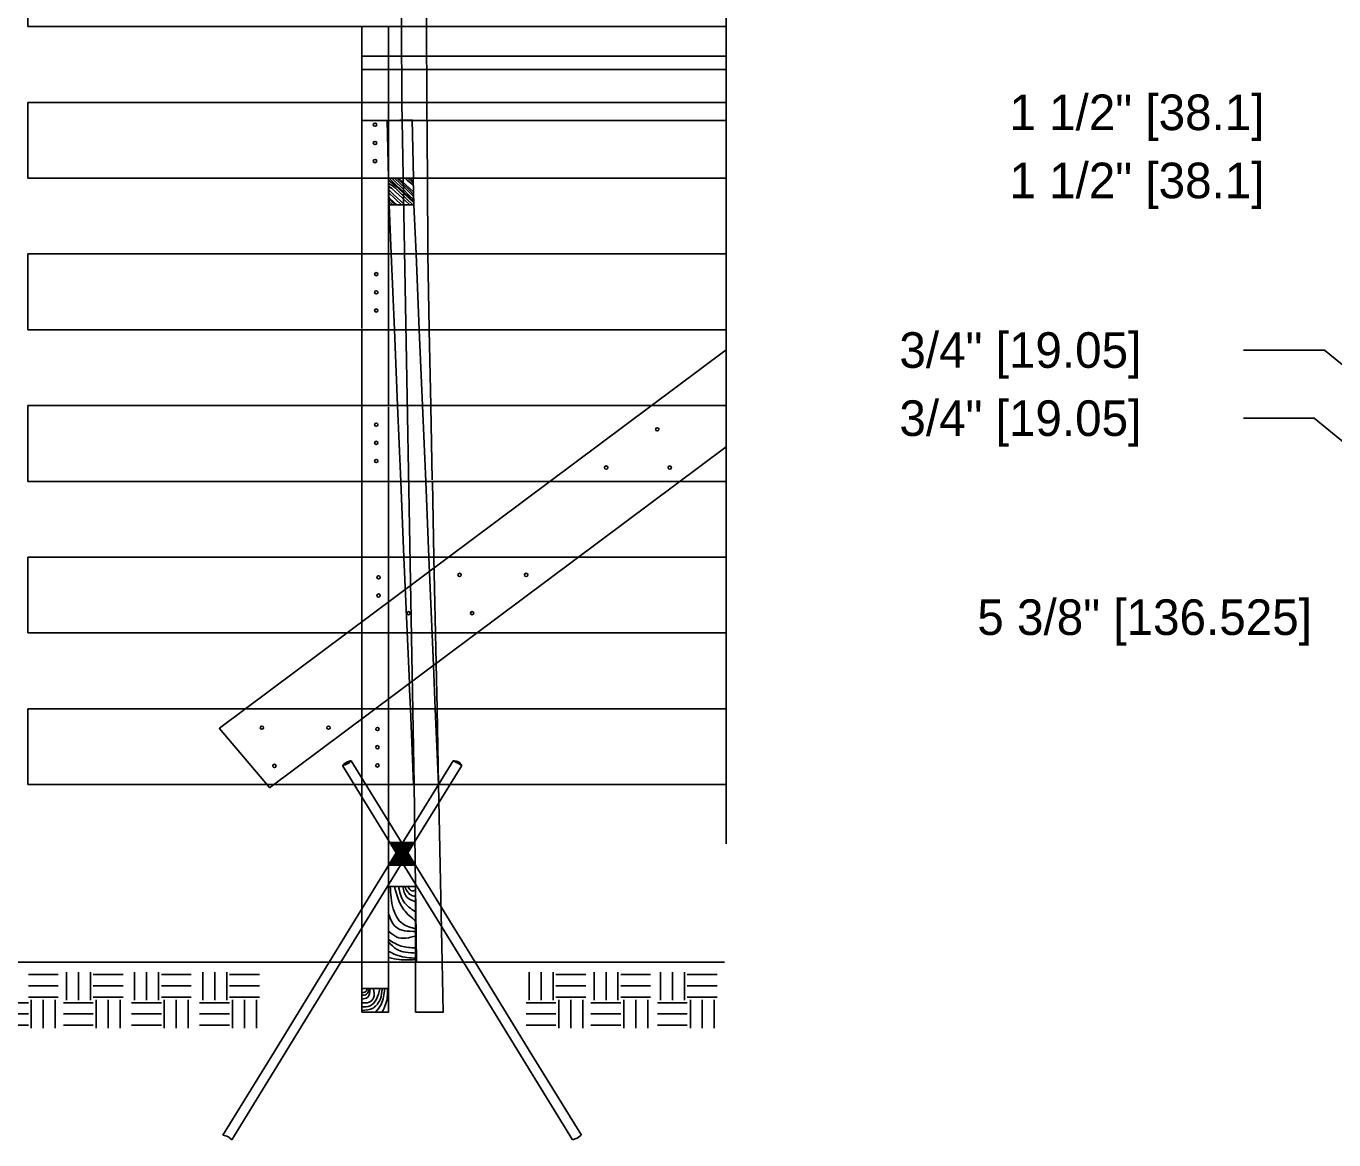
# Model space of a CAD drawing. Extents: x 49991.4 to 50021, y 49987.6 to 50011.4.
# Drawn here: x 50005.062 to 50007.266, y 49994.072 to 49995.949 of the extents above; entities that cross this region are included whole.
import ezdxf

# ---------------------------------------------------------------- set-up
doc = ezdxf.new("R2010")
doc.units = 0
for name, color, linetype in [('Level 1', 7, 'Continuous'), ('Level 2', 7, 'Continuous'), ('Level 3', 7, 'Continuous'), ('Level 4', 7, 'Continuous'), ('Level 6', 7, 'Continuous')]:
    doc.layers.add(name, color=color, linetype=linetype)

msp = doc.modelspace()

# ---------------------------------------------------------------- linework, layer by layer
at = {"layer": 'Level 1'}
for p, q in [((50005.0654, 49996.076), (50005.0654, 49995.9482)), ((50005.0654, 49995.9482), (50006.2419, 49995.9482)), ((50005.6278, 49995.9482), (50005.6278, 49995.8204)), ((50005.6732, 49995.8204), (50005.6732, 49995.9482)), ((50005.6955, 49995.8204), (50005.6947, 49995.9482)), ((50005.7375, 49995.8204), (50005.7367, 49995.9482)), ((50005.6732, 49995.898), (50005.695, 49995.898)), ((50005.737, 49995.898), (50006.2419, 49995.898)), ((50005.6952, 49995.8757), (50005.6732, 49995.8757)), ((50005.7372, 49995.8757), (50006.2419, 49995.8757)), ((50005.0654, 49995.8204), (50005.0654, 49995.6928)), ((50005.0654, 49995.8204), (50006.2419, 49995.8204)), ((50005.0654, 49995.6928), (50006.2419, 49995.6928)), ((50005.6278, 49995.6936), (50005.6278, 49995.5646)), ((50005.6738, 49995.6479), (50005.6729, 49995.6928)), ((50005.6732, 49995.6928), (50005.6732, 49995.5646)), ((50005.7158, 49995.6479), (50005.7146, 49995.6928)), ((50005.7392, 49995.565), (50005.7384, 49995.6928)), ((50005.6738, 49995.6479), (50005.7158, 49995.6479)), ((50005.6738, 49995.6479), (50005.6773, 49995.565)), ((50005.7158, 49995.6479), (50005.7193, 49995.565)), ((50005.0654, 49995.565), (50005.0654, 49995.4372)), ((50005.0654, 49995.565), (50006.2419, 49995.565)), ((50005.6773, 49995.565), (50005.6828, 49995.4372)), ((50005.0654, 49995.4372), (50006.2419, 49995.4372)), ((50005.6278, 49995.4372), (50005.6278, 49995.3094)), ((50005.6732, 49995.3094), (50005.6732, 49995.4372)), ((50005.6828, 49995.4372), (50005.6881, 49995.3094)), ((50005.7248, 49995.4372), (50005.7301, 49995.3094)), ((50005.7443, 49995.3094), (50005.7417, 49995.4372)), ((50005.3881, 49994.7655), (50006.2419, 49995.4032)), ((50005.0654, 49995.3094), (50005.0654, 49995.1816)), ((50005.0654, 49995.3094), (50006.1163, 49995.3094)), ((50005.4726, 49994.6654), (50006.2419, 49995.2399)), ((50005.0654, 49995.1816), (50005.9454, 49995.1816)), ((50005.6278, 49995.1816), (50005.6278, 49995.054)), ((50005.6732, 49995.054), (50005.6732, 49995.1816)), ((50005.6936, 49995.1816), (50005.6989, 49995.054)), ((50005.7356, 49995.1816), (50005.7409, 49995.054)), ((50005.7493, 49995.054), (50005.747, 49995.1816)), ((50006.1638, 49995.1816), (50006.2419, 49995.1816)), ((50005.0654, 49995.054), (50005.0654, 49994.9262)), ((50005.7743, 49995.054), (50005.0654, 49995.054)), ((50005.9927, 49995.054), (50006.2419, 49995.054)), ((50005.0654, 49994.9262), (50005.6032, 49994.9262)), ((50005.8218, 49994.9262), (50006.2419, 49994.9262)), ((50005.7487, 49994.8716), (50005.7518, 49994.7984)), ((50005.7547, 49994.7984), (50005.753, 49994.8748)), ((50005.708, 49994.8412), (50005.7098, 49994.7984)), ((50005.6732, 49994.7984), (50005.6732, 49994.8152)), ((50005.0654, 49994.7984), (50005.0654, 49994.6706)), ((50005.0654, 49994.7984), (50005.4321, 49994.7984)), ((50005.4215, 49994.7984), (50005.244, 49994.7984)), ((50005.6507, 49994.7984), (50006.2419, 49994.7984)), ((50005.4723, 49994.6658), (50005.3878, 49994.7659)), ((50005.686, 49994.5554), (50005.5954, 49994.703)), ((50005.6102, 49994.7109), (50005.6959, 49994.5714)), ((50005.7816, 49994.7109), (50005.6959, 49994.5714)), ((50005.7057, 49994.5554), (50005.7963, 49994.703)), ((50005.0654, 49994.6706), (50006.2419, 49994.6706)), ((50005.3092, 49994.6706), (50005.244, 49994.6706)), ((50005.5503, 49994.6706), (50005.3092, 49994.6706)), ((50005.5503, 49994.6706), (50005.6576, 49994.6706)), ((50005.6278, 49994.6706), (50005.6278, 49994.3711)), ((50005.6732, 49994.3711), (50005.6732, 49994.6706)), ((50005.7162, 49994.6706), (50005.7202, 49994.3711)), ((50005.7632, 49994.3711), (50005.7571, 49994.6706)), ((50005.6752, 49994.5731), (50005.7164, 49994.5731)), ((50005.6765, 49994.571), (50005.7152, 49994.571)), ((50005.6778, 49994.5688), (50005.7138, 49994.5688)), ((50005.6791, 49994.5667), (50005.7126, 49994.5667)), ((50005.6804, 49994.5645), (50005.7112, 49994.5645)), ((50005.6817, 49994.5624), (50005.71, 49994.5624)), ((50005.686, 49994.5554), (50005.5728, 49994.3711)), ((50005.6773, 49994.5411), (50005.7145, 49994.5411)), ((50005.6786, 49994.5433), (50005.7132, 49994.5433)), ((50005.6799, 49994.5454), (50005.7119, 49994.5454)), ((50005.6812, 49994.5475), (50005.7106, 49994.5475)), ((50005.6825, 49994.5497), (50005.7093, 49994.5497)), ((50005.683, 49994.5603), (50005.7086, 49994.5603)), ((50005.6838, 49994.5518), (50005.708, 49994.5518)), ((50005.6843, 49994.5581), (50005.7074, 49994.5581)), ((50005.6851, 49994.554), (50005.7066, 49994.554)), ((50005.6856, 49994.556), (50005.706, 49994.556)), ((50005.7055, 49994.5555), (50005.8189, 49994.3711)), ((50005.5924, 49994.3711), (50005.6958, 49994.5394)), ((50005.6734, 49994.5347), (50005.7184, 49994.5347)), ((50005.6747, 49994.5368), (50005.7171, 49994.5368)), ((50005.676, 49994.539), (50005.7158, 49994.539)), ((50005.7993, 49994.3711), (50005.6958, 49994.5394)), ((50005.7185, 49994.4988), (50005.6732, 49994.4988)), ((50005.6732, 49994.4988), (50005.6732, 49994.3711)), ((50005.6732, 49994.4988), (50005.7185, 49994.4988)), ((50005.6732, 49994.3711), (50005.6732, 49994.4988)), ((50005.7185, 49994.3711), (50005.7185, 49994.4988)), ((49999.8901, 49994.3711), (50006.2392, 49994.3711)), ((50005.6732, 49994.3711), (50005.7185, 49994.3711)), ((50005.6732, 49994.3711), (50005.7185, 49994.3711)), ((50005.0661, 49994.3503), (50005.1164, 49994.3503)), ((50005.1305, 49994.3547), (50005.1305, 49994.3074)), ((50005.1507, 49994.3547), (50005.1507, 49994.3074)), ((50005.1708, 49994.3547), (50005.1708, 49994.3074)), ((50005.1755, 49994.3503), (50005.2258, 49994.3503)), ((50005.2452, 49994.3547), (50005.2452, 49994.3074)), ((50005.2654, 49994.3547), (50005.2654, 49994.3074)), ((50005.2855, 49994.3547), (50005.2855, 49994.3074)), ((50005.2902, 49994.3503), (50005.3405, 49994.3503)), ((50005.3601, 49994.3547), (50005.3601, 49994.3074)), ((50005.3801, 49994.3547), (50005.3801, 49994.3074)), ((50005.4003, 49994.3547), (50005.4003, 49994.3074)), ((50005.405, 49994.3503), (50005.4554, 49994.3503)), ((50005.9099, 49994.3547), (50005.9099, 49994.3074)), ((50005.93, 49994.3547), (50005.93, 49994.3074)), ((50005.9502, 49994.3547), (50005.9502, 49994.3074)), ((50005.9549, 49994.3503), (50006.0052, 49994.3503)), ((50006.0194, 49994.3547), (50006.0194, 49994.3074)), ((50006.0395, 49994.3547), (50006.0395, 49994.3074)), ((50006.0595, 49994.3547), (50006.0595, 49994.3074)), ((50006.0642, 49994.3503), (50006.1146, 49994.3503)), ((50006.1314, 49994.3547), (50006.1314, 49994.3074)), ((50006.1516, 49994.3547), (50006.1516, 49994.3074)), ((50006.1717, 49994.3547), (50006.1717, 49994.3074)), ((50006.1764, 49994.3503), (50006.2267, 49994.3503)), ((50005.0661, 49994.3314), (50005.1164, 49994.3314)), ((50005.1755, 49994.3314), (50005.2258, 49994.3314)), ((50005.2902, 49994.3314), (50005.3405, 49994.3314)), ((50005.405, 49994.3314), (50005.4554, 49994.3314)), ((50005.9549, 49994.3314), (50006.0052, 49994.3314)), ((50006.0642, 49994.3314), (50006.1146, 49994.3314)), ((50006.1764, 49994.3314), (50006.2267, 49994.3314)), ((50005.0156, 49994.3029), (50005.0661, 49994.3029)), ((50005.0661, 49994.3124), (50005.1164, 49994.3124)), ((50005.071, 49994.3078), (50005.071, 49994.2604)), ((50005.0912, 49994.3078), (50005.0912, 49994.2604)), ((50005.1113, 49994.3078), (50005.1113, 49994.2604)), ((50005.1252, 49994.3029), (50005.1755, 49994.3029)), ((50005.1755, 49994.3124), (50005.2258, 49994.3124)), ((50005.1806, 49994.3078), (50005.1806, 49994.2604)), ((50005.2006, 49994.3078), (50005.2006, 49994.2604)), ((50005.2208, 49994.3078), (50005.2208, 49994.2604)), ((50005.2399, 49994.3029), (50005.2902, 49994.3029)), ((50005.2902, 49994.3124), (50005.3405, 49994.3124)), ((50005.2952, 49994.3078), (50005.2952, 49994.2604)), ((50005.3154, 49994.3078), (50005.3154, 49994.2604)), ((50005.3356, 49994.3078), (50005.3356, 49994.2604)), ((50005.3547, 49994.3029), (50005.405, 49994.3029)), ((50005.405, 49994.3124), (50005.4554, 49994.3124)), ((50005.41, 49994.3078), (50005.41, 49994.2604)), ((50005.4302, 49994.3078), (50005.4302, 49994.2604)), ((50005.4503, 49994.3078), (50005.4503, 49994.2604)), ((50005.9046, 49994.3029), (50005.9549, 49994.3029)), ((50005.9549, 49994.3124), (50006.0052, 49994.3124)), ((50005.9599, 49994.3078), (50005.9599, 49994.2604)), ((50005.9801, 49994.3078), (50005.9801, 49994.2604)), ((50006.0001, 49994.3078), (50006.0001, 49994.2604)), ((50006.0139, 49994.3029), (50006.0642, 49994.3029)), ((50006.0642, 49994.3124), (50006.1146, 49994.3124)), ((50006.0693, 49994.3078), (50006.0693, 49994.2604)), ((50006.0894, 49994.3078), (50006.0894, 49994.2604)), ((50006.1096, 49994.3078), (50006.1096, 49994.2604)), ((50006.1261, 49994.3029), (50006.1764, 49994.3029)), ((50006.1764, 49994.3124), (50006.2267, 49994.3124)), ((50006.1815, 49994.3078), (50006.1815, 49994.2604)), ((50006.2015, 49994.3078), (50006.2015, 49994.2604)), ((50006.2216, 49994.3078), (50006.2216, 49994.2604)), ((50005.0156, 49994.2841), (50005.0661, 49994.2841)), ((50005.1252, 49994.2841), (50005.1755, 49994.2841)), ((50005.2399, 49994.2841), (50005.2902, 49994.2841)), ((50005.3547, 49994.2841), (50005.405, 49994.2841)), ((50005.9046, 49994.2841), (50005.9549, 49994.2841)), ((50006.0139, 49994.2841), (50006.0642, 49994.2841)), ((50006.1261, 49994.2841), (50006.1764, 49994.2841)), ((50005.0156, 49994.2651), (50005.0661, 49994.2651)), ((50005.1252, 49994.2651), (50005.1755, 49994.2651)), ((50005.2399, 49994.2651), (50005.2902, 49994.2651)), ((50005.3547, 49994.2651), (50005.405, 49994.2651)), ((50005.9046, 49994.2651), (50005.9549, 49994.2651)), ((50006.0139, 49994.2651), (50006.0642, 49994.2651)), ((50006.1261, 49994.2651), (50006.1764, 49994.2651))]:
    msp.add_line(p, q, dxfattribs=at)
for points in [[(50005.7158, 49995.6512), (50005.6977, 49995.6678), (50005.6855, 49995.6789), (50005.6732, 49995.689), (50005.6729, 49995.6894)], [(50005.7156, 49995.6536), (50005.6989, 49995.6691), (50005.6868, 49995.6799), (50005.6767, 49995.6898), (50005.674, 49995.6926)], [(50005.7155, 49995.6562), (50005.7077, 49995.6636), (50005.6968, 49995.6744), (50005.6826, 49995.6887), (50005.6783, 49995.6928)], [(50005.7155, 49995.6614), (50005.7016, 49995.6751), (50005.6829, 49995.6928), (50005.6829, 49995.6928)], [(50005.7155, 49995.6644), (50005.7075, 49995.6729), (50005.6867, 49995.6927)], [(50005.7154, 49995.6688), (50005.7084, 49995.6756), (50005.6962, 49995.6868), (50005.69, 49995.6928)], [(50005.7149, 49995.6801), (50005.7137, 49995.6812), (50005.7042, 49995.6895), (50005.7011, 49995.6928)], [(50005.715, 49995.6838), (50005.7137, 49995.685), (50005.7053, 49995.6928)], [(50005.7147, 49995.6871), (50005.7094, 49995.6919), (50005.7087, 49995.6927)], [(50005.7138, 49995.6479), (50005.6927, 49995.6682), (50005.6841, 49995.6766), (50005.6789, 49995.6803), (50005.675, 49995.6824), (50005.673, 49995.6842)], [(50005.7075, 49995.6487), (50005.6849, 49995.6698), (50005.6784, 49995.6752), (50005.6732, 49995.6792)], [(50005.7003, 49995.6479), (50005.6807, 49995.6657), (50005.6733, 49995.6728)], [(50005.695, 49995.6479), (50005.6734, 49995.6679), (50005.6734, 49995.6679)], [(50005.6871, 49995.6479), (50005.6747, 49995.6592), (50005.6736, 49995.6607)], [(50005.684, 49995.6479), (50005.6791, 49995.6522), (50005.6737, 49995.6574)], [(50005.6797, 49995.6479), (50005.679, 49995.6484), (50005.6737, 49995.6531)]]:
    msp.add_lwpolyline(points, dxfattribs=at)
for centre, major_axis in [((50005.6502, 49995.7827), (0.00285, 0)), ((50005.6502, 49995.752), (0.00285, 0)), ((50005.6502, 49995.7214), (0.00285, 0)), ((50005.6522, 49995.5309), (0.00285, 0)), ((50005.6522, 49995.5002), (0.00285, 0)), ((50005.6522, 49995.4696), (0.00285, 0)), ((50005.6522, 49995.2772), (0.00285, 0)), ((50006.1258, 49995.2694), (-0.00285, 0)), ((50005.6522, 49995.2466), (0.00285, 0)), ((50005.6522, 49995.2159), (0.00285, 0)), ((50006.0397, 49995.2049), (-0.00285, 0)), ((50006.1468, 49995.2049), (-0.00285, 0)), ((50005.7927, 49995.024), (-0.00285, 0)), ((50005.9049, 49995.024), (-0.00285, 0)), ((50005.6562, 49995.0198), (0.00285, 0)), ((50005.6562, 49994.9892), (0.00285, 0)), ((50005.7067, 49994.9595), (-0.00285, 0)), ((50005.8138, 49994.9595), (-0.00285, 0)), ((50005.4596, 49994.7665), (-0.00285, 0)), ((50005.5718, 49994.7665), (-0.00285, 0)), ((50005.6542, 49994.7643), (0.00285, 0)), ((50005.6542, 49994.7336), (0.00285, 0)), ((50005.4807, 49994.7021), (-0.00285, 0)), ((50005.6542, 49994.7029), (0.00285, 0))]:
    msp.add_ellipse(centre, major_axis=major_axis, ratio=0.940299, dxfattribs=at)
for points in [[(50005.5954, 49994.703), (50005.6044, 49994.7059), (50005.6102, 49994.7109)], [(50005.5954, 49994.703), (50005.6037, 49994.7091), (50005.6102, 49994.7109)], [(50005.7816, 49994.7109), (50005.7916, 49994.7082), (50005.7963, 49994.703)], [(50005.7816, 49994.7109), (50005.7889, 49994.7071), (50005.7963, 49994.703)], [(50005.6758, 49994.499), (50005.681, 49994.461), (50005.6963, 49994.4363), (50005.7198, 49994.4275)], [(50005.6829, 49994.499), (50005.6986, 49994.4598), (50005.7193, 49994.4401)], [(50005.6898, 49994.4995), (50005.6986, 49994.4731), (50005.718, 49994.4566)], [(50005.6968, 49994.4985), (50005.704, 49994.4809), (50005.7187, 49994.4731)], [(50005.6998, 49994.4995), (50005.7103, 49994.4847), (50005.718, 49994.482)], [(50005.7057, 49994.499), (50005.7127, 49994.4913), (50005.718, 49994.4924)], [(50005.6734, 49994.4517), (50005.6851, 49994.4307), (50005.7187, 49994.4231)], [(50005.6729, 49994.4093), (50005.6945, 49994.3984), (50005.7187, 49994.3955)], [(50005.6734, 49994.4231), (50005.6869, 49994.4137), (50005.7193, 49994.4154)], [(50005.6734, 49994.405), (50005.6863, 49994.3933), (50005.7193, 49994.3868)], [(50005.6734, 49994.3895), (50005.6893, 49994.3824), (50005.7193, 49994.378)], [(50005.6734, 49994.379), (50005.6911, 49994.3757), (50005.718, 49994.3757)]]:
    msp.add_spline(points, degree=3, dxfattribs=at)
at = {"layer": 'Level 3'}
for p, q in [((50007.2498, 49995.403), (50007.1137, 49995.403)), ((50007.4211, 49995.2631), (50007.2498, 49995.403)), ((50007.2324, 49995.2882), (50007.1137, 49995.2882)), ((50007.3708, 49995.1752), (50007.2324, 49995.2882))]:
    msp.add_line(p, q, dxfattribs=at)
at = {"layer": 'Level 4'}
for p, q in [((50005.6947, 49995.9482), (50005.694, 49996.076)), ((50005.7367, 49995.9482), (50005.736, 49996.076)), ((50005.6278, 49995.898), (50005.6732, 49995.898)), ((50005.695, 49995.898), (50005.737, 49995.898)), ((50005.6278, 49995.8757), (50005.6732, 49995.8757)), ((50005.6952, 49995.8757), (50005.7372, 49995.8757)), ((50005.6278, 49995.8194), (50005.6278, 49995.6936)), ((50005.6732, 49995.6928), (50005.6732, 49995.8187)), ((50005.6955, 49995.8204), (50005.7161, 49994.6706)), ((50005.7384, 49995.6928), (50005.7375, 49995.8204)), ((50005.6278, 49995.7899), (50006.2419, 49995.7899)), ((50005.7129, 49995.7909), (50005.6707, 49995.7901)), ((50005.6707, 49995.7901), (50005.6729, 49995.6928)), ((50005.7149, 49995.6928), (50005.7129, 49995.7909)), ((50005.6278, 49995.5646), (50005.6278, 49995.4393)), ((50005.6732, 49995.4382), (50005.6732, 49995.565)), ((50005.7193, 49995.565), (50005.7248, 49995.4372)), ((50005.7417, 49995.4382), (50005.7392, 49995.565)), ((50005.6278, 49995.3085), (50005.6278, 49995.1829)), ((50005.6732, 49995.1829), (50005.6732, 49995.3074)), ((50005.6881, 49995.3094), (50005.6936, 49995.1816)), ((50005.7301, 49995.3094), (50005.7356, 49995.1816)), ((50005.7467, 49995.184), (50005.7443, 49995.3085)), ((50006.2419, 49995.3094), (50006.1163, 49995.3094)), ((50005.9454, 49995.1816), (50006.1638, 49995.1816)), ((50005.6278, 49995.0528), (50005.6278, 49994.9269)), ((50005.6732, 49994.8152), (50005.6732, 49995.0521)), ((50005.6989, 49995.054), (50005.7081, 49994.8412)), ((50005.7409, 49995.054), (50005.7487, 49994.8716)), ((50005.753, 49994.8748), (50005.7493, 49995.0521)), ((50005.7743, 49995.054), (50005.9927, 49995.054)), ((50005.6032, 49994.9262), (50005.8218, 49994.9262)), ((50005.6278, 49994.9262), (50005.6278, 49994.7984)), ((50005.6507, 49994.7984), (50005.4215, 49994.7984)), ((50005.6278, 49994.7984), (50005.6278, 49994.6706)), ((50005.6732, 49994.6706), (50005.6732, 49994.7984)), ((50005.7098, 49994.7984), (50005.7152, 49994.6706)), ((50005.7518, 49994.7984), (50005.7571, 49994.6706)), ((50005.7571, 49994.6706), (50005.7547, 49994.7984)), ((50005.5728, 49994.3711), (50005.4762, 49994.2135)), ((50005.4909, 49994.2056), (50005.5924, 49994.3711)), ((50005.6278, 49994.3711), (50005.6278, 49994.3272)), ((50005.6732, 49994.3272), (50005.6732, 49994.3711)), ((50005.7184, 49994.3711), (50005.7184, 49994.2873)), ((50005.7649, 49994.2873), (50005.7632, 49994.3711)), ((50005.8999, 49994.2071), (50005.7993, 49994.3711)), ((50005.8189, 49994.3711), (50005.9146, 49994.2152)), ((50005.7184, 49994.2873), (50005.7658, 49994.2873)), ((50005.4761, 49994.2136), (50005.3938, 49994.0796)), ((50005.9146, 49994.2152), (50005.9979, 49994.0796)), ((50005.4089, 49994.0719), (50005.4909, 49994.2056)), ((50005.983, 49994.0719), (50005.8999, 49994.2071))]:
    msp.add_line(p, q, dxfattribs=at)
msp.add_lwpolyline([(50005.6278, 49994.2873), (50005.6732, 49994.2873), (50005.6732, 49994.3272), (50005.6278, 49994.3272)], close=True, dxfattribs=at)
msp.add_lwpolyline([(50005.983, 49994.0719), (50005.9908, 49994.0749), (50005.9978, 49994.0796)], dxfattribs=at)
for points in [[(50005.6275, 49994.2958), (50005.6422, 49994.298), (50005.6586, 49994.3266)], [(50005.6275, 49994.2958), (50005.6422, 49994.298), (50005.6586, 49994.3266)], [(50005.628, 49994.32), (50005.6357, 49994.3228), (50005.6369, 49994.3266)], [(50005.628, 49994.3156), (50005.6357, 49994.3172), (50005.6404, 49994.3266)], [(50005.628, 49994.309), (50005.6374, 49994.3118), (50005.6422, 49994.3266)], [(50005.628, 49994.3029), (50005.6404, 49994.304), (50005.6476, 49994.3113), (50005.6476, 49994.3266)], [(50005.628, 49994.32), (50005.6357, 49994.3228), (50005.6369, 49994.3266)], [(50005.628, 49994.3156), (50005.6357, 49994.3172), (50005.6404, 49994.3266)], [(50005.628, 49994.309), (50005.6374, 49994.3118), (50005.6422, 49994.3266)], [(50005.628, 49994.3029), (50005.6404, 49994.304), (50005.6476, 49994.3113), (50005.6476, 49994.3266)], [(50005.628, 49994.2898), (50005.6469, 49994.2941), (50005.6592, 49994.3096), (50005.6621, 49994.3261)], [(50005.628, 49994.2898), (50005.6469, 49994.2941), (50005.6592, 49994.3096), (50005.6621, 49994.3261)], [(50005.6516, 49994.2876), (50005.6604, 49994.3002), (50005.6663, 49994.3266)], [(50005.6516, 49994.2876), (50005.6604, 49994.3002), (50005.6663, 49994.3266)], [(50005.6621, 49994.2876), (50005.6681, 49994.3002), (50005.6715, 49994.3271)], [(50005.6621, 49994.2876), (50005.6681, 49994.3002), (50005.6715, 49994.3271)], [(50005.3938, 49994.0796), (50005.4026, 49994.0769), (50005.4089, 49994.0719)]]:
    msp.add_spline(points, degree=3, dxfattribs=at)
at = {"layer": 'Level 6'}
msp.add_line((50006.2419, 49996.0756), (50006.2419, 49994.5706), dxfattribs=at)

# ---------------------------------------------------------------- texts
at = {"layer": 'Level 2'}
for s, p in [('1 1/2" [38.1]', (50006.719, 49995.7736)), ('1 1/2" [38.1]', (50006.719, 49995.6588)), ('3/4" [19.05]', (50006.5337, 49995.373)), ('3/4" [19.05]', (50006.5337, 49995.2582)), ('5 3/8" [136.525]', (50006.665, 49994.9228))]:
    msp.add_text(s, height=0.06, dxfattribs=at).set_placement(p)

doc.saveas('drawing.dxf')
